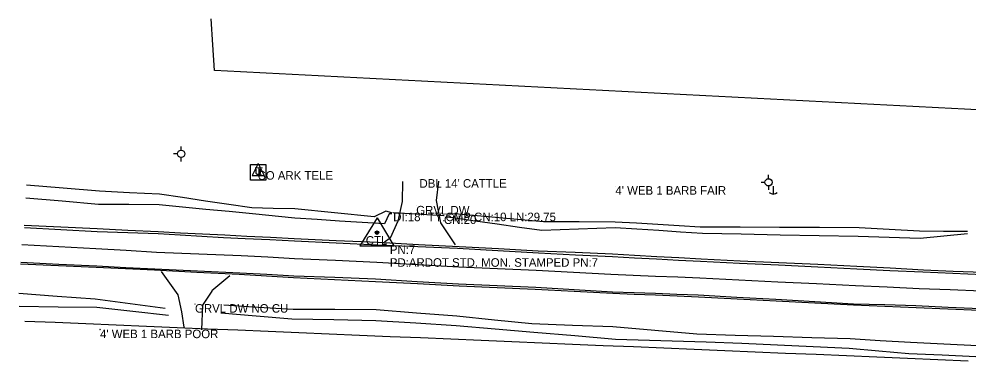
# Model space of a CAD drawing. Extents: x 1138803 to 1169983, y 1655906 to 1658226.
# Drawn here: x 1148268 to 1148823, y 1657454 to 1657654 of the extents above; entities that cross this region are included whole.
import ezdxf

# ---------------------------------------------------------------- set-up
doc = ezdxf.new("R2010")
doc.units = 0
for name, color, linetype in [('S_DITCHLINE', 7, 'Continuous'), ('S_DRG_PT_SYM', 7, 'Continuous'), ('S_DRIVEWAY', 7, 'Continuous'), ('S_EDGE_PAVEMENT', 7, 'Continuous'), ('S_GATE_ANNOT', 7, 'Continuous'), ('S_MSC_PT_SYM', 7, 'Continuous'), ('S_PAVEMENT_CROWN', 7, 'Continuous'), ('S_PRIMARY_CTL', 7, 'Continuous'), ('S_PRIMARY_CTL_ANNOT', 7, 'Continuous'), ('S_SHOULDER', 7, 'Continuous'), ('S_SIDE_DRAIN', 7, 'Continuous'), ('S_SIDE_DRAIN_ANNOT', 7, 'Continuous'), ('S_SURVEY_TEXT_ANNOT', 7, 'Continuous'), ('S_TELEPHONE_UTILITIES', 7, 'Continuous'), ('S_TREE', 7, 'Continuous'), ('S_UNDERGROUND_CABLE', 7, 'Continuous'), ('S_UTILITY_POLE', 7, 'Continuous'), ('S_UTILITY_POLE_ANNOT', 7, 'Continuous')]:
    doc.layers.add(name, color=color, linetype=linetype)

msp = doc.modelspace()

# ---------------------------------------------------------------- linework, layer by layer
at = {"layer": 'S_DITCHLINE'}
for points in [[(1148485.93, 1657540.92), (1148482.4, 1657541.89), (1148475.52, 1657538.62), (1148452.31, 1657540.88), (1148429.09, 1657543.15), (1148416.52, 1657543.47), (1148403.94, 1657543.8), (1148390.43, 1657545.79), (1148376.92, 1657547.79), (1148363.4, 1657549.79), (1148349.89, 1657551.79), (1148332.37, 1657552.66), (1148314.86, 1657553.54), (1148293.48, 1657555.35), (1148272.1, 1657557.17)], [(1148486.05, 1657540.23), (1148484.33, 1657540.22), (1148481.66, 1657534.47), (1148468.54, 1657535.28), (1148455.41, 1657536.08), (1148442.29, 1657536.89), (1148429.17, 1657537.7), (1148404.43, 1657540.36), (1148390.74, 1657541.65), (1148377.05, 1657542.93), (1148363.36, 1657544.22), (1148349.67, 1657545.51), (1148331.96, 1657545.67), (1148314.25, 1657545.83), (1148292.97, 1657547.67), (1148271.7, 1657549.5)], [(1148823.01, 1657528.61), (1148809.18, 1657527.24), (1148795.36, 1657525.87), (1148777.18, 1657526.41), (1148759, 1657526.95), (1148736.19, 1657527.41), (1148713.38, 1657527.87), (1148690.57, 1657528.33), (1148667.76, 1657528.79), (1148654.98, 1657529.62), (1148642.2, 1657530.45), (1148629.42, 1657531.28), (1148616.63, 1657532.11), (1148595.19, 1657531.29), (1148573.75, 1657530.47), (1148560.72, 1657532.34), (1148547.7, 1657534.2), (1148534.68, 1657536.07), (1148521.65, 1657537.93), (1148518.25, 1657538.29)], [(1148822.92, 1657529.88), (1148808.87, 1657529.97), (1148794.82, 1657530.07), (1148777.14, 1657531.08), (1148759.47, 1657532.09), (1148736.25, 1657532.21), (1148713.02, 1657532.33), (1148689.8, 1657532.45), (1148666.57, 1657532.57), (1148654.09, 1657533.3), (1148641.6, 1657534.04), (1148629.12, 1657534.77), (1148616.64, 1657535.51), (1148595.66, 1657535.58), (1148574.69, 1657535.66), (1148561.75, 1657536.84), (1148548.8, 1657538.03), (1148535.86, 1657539.21), (1148522.91, 1657540.4), (1148519.12, 1657539.89)], [(1148353.19, 1657484.82), (1148332.74, 1657487.54), (1148312.28, 1657490.26), (1148289.97, 1657492), (1148267.65, 1657493.74)], [(1148828.82, 1657463.09), (1148809.2, 1657464), (1148789.58, 1657464.92), (1148771.95, 1657465.99), (1148754.31, 1657467.06), (1148731.84, 1657467.76), (1148709.38, 1657468.47), (1148686.91, 1657469.18), (1148664.44, 1657469.89), (1148639.92, 1657472.02), (1148615.4, 1657474.15), (1148591.67, 1657474.99), (1148567.94, 1657475.83), (1148545.99, 1657478.12), (1148524.04, 1657480.4), (1148500.45, 1657482.25), (1148476.87, 1657484.1), (1148452.54, 1657484.22), (1148428.21, 1657484.35), (1148407.86, 1657485.56), (1148387.52, 1657486.78)], [(1148355.23, 1657480.77), (1148334.27, 1657483.12), (1148313.32, 1657485.47), (1148290.56, 1657485.74), (1148267.81, 1657486.01)], [(1148827.85, 1657456.65), (1148808.21, 1657457.48), (1148788.57, 1657458.32), (1148771.11, 1657459.92), (1148753.64, 1657461.51), (1148732.72, 1657462.45), (1148711.8, 1657463.39), (1148690.87, 1657464.33), (1148669.95, 1657465.26), (1148656.69, 1657465.65), (1148643.43, 1657466.03), (1148630.17, 1657466.42), (1148616.91, 1657466.8), (1148593.02, 1657468.8), (1148569.14, 1657470.79), (1148546.37, 1657472.78), (1148523.6, 1657474.78), (1148500.06, 1657476.24), (1148476.52, 1657477.7), (1148451.98, 1657478.17), (1148427.45, 1657478.63), (1148406.61, 1657480.36), (1148385.76, 1657482.09)]]:
    msp.add_lwpolyline(points, dxfattribs=at)
at = {"layer": 'S_DRG_PT_SYM'}
for points in [[(1148486.76, 1657541.01), (1148486.76, 1657541.06), (1148486.76, 1657541.01), (1148486.71, 1657541.01), (1148486.76, 1657541.01), (1148486.76, 1657540.96), (1148486.76, 1657541.01), (1148486.81, 1657541.01)], [(1148516.47, 1657539.33), (1148516.47, 1657539.38), (1148516.47, 1657539.33), (1148516.42, 1657539.33), (1148516.47, 1657539.33), (1148516.47, 1657539.28), (1148516.47, 1657539.33), (1148516.52, 1657539.33)]]:
    msp.add_lwpolyline(points, dxfattribs=at)
at = {"layer": 'S_DRIVEWAY'}
for points in [[(1148492.21, 1657559.26), (1148491.96, 1657547.46), (1148489.44, 1657536.08), (1148485.02, 1657526.13), (1148481.69, 1657523.77)], [(1148523.19, 1657522.09), (1148514.68, 1657535.04), (1148512.19, 1657548.05), (1148513.41, 1657559.47)], [(1148364.29, 1657473.87), (1148363.09, 1657482.96), (1148360.77, 1657492.85), (1148351.07, 1657506.46)], [(1148391.01, 1657504.01), (1148380.57, 1657495.14), (1148380.57, 1657495.03), (1148375.15, 1657486.8), (1148374.47, 1657472.43)]]:
    msp.add_lwpolyline(points, dxfattribs=at)
at = {"layer": 'S_EDGE_PAVEMENT'}
for points in [[(1148831.93, 1657504.6), (1148814.37, 1657505.33), (1148796.81, 1657506.06), (1148777.48, 1657507.02), (1148758.15, 1657507.98), (1148735.28, 1657509.08), (1148712.42, 1657510.18), (1148689.55, 1657511.27), (1148666.68, 1657512.37), (1148653.78, 1657513.05), (1148640.88, 1657513.73), (1148627.98, 1657514.41), (1148615.07, 1657515.1), (1148593.4, 1657516.16), (1148571.73, 1657517.22), (1148548.08, 1657518.57), (1148524.43, 1657519.93), (1148501.08, 1657520.94), (1148477.73, 1657521.95), (1148453.38, 1657523.17), (1148429.04, 1657524.38), (1148414.56, 1657524.99), (1148400.08, 1657525.59), (1148387.37, 1657526.33), (1148374.66, 1657527.07), (1148361.95, 1657527.81), (1148349.23, 1657528.56), (1148331.35, 1657529.19), (1148313.46, 1657529.83), (1148292.18, 1657530.97), (1148270.91, 1657532.11)], [(1148830.37, 1657484.61), (1148811.58, 1657485.5), (1148792.8, 1657486.39), (1148774.53, 1657486.94), (1148756.26, 1657487.5), (1148733.52, 1657488.79), (1148710.78, 1657490.07), (1148688.04, 1657491.36), (1148665.29, 1657492.65), (1148652.78, 1657493.12), (1148640.27, 1657493.59), (1148627.75, 1657494.06), (1148615.24, 1657494.52), (1148592.75, 1657495.85), (1148570.27, 1657497.18), (1148547.66, 1657498.14), (1148525.05, 1657499.09), (1148500.75, 1657500.55), (1148476.45, 1657502.01), (1148452.49, 1657502.94), (1148428.53, 1657503.86), (1148412.73, 1657504.74), (1148396.93, 1657505.61), (1148372.09, 1657506.75), (1148347.24, 1657507.89), (1148330.2, 1657508.73), (1148313.16, 1657509.58), (1148290.96, 1657510.7), (1148268.76, 1657511.81)]]:
    msp.add_lwpolyline(points, dxfattribs=at)
at = {"layer": 'S_MSC_PT_SYM'}
for points in [[(1148502.14, 1657560.62), (1148502.14, 1657560.67), (1148502.14, 1657560.62), (1148502.09, 1657560.62), (1148502.14, 1657560.62), (1148502.14, 1657560.57), (1148502.14, 1657560.62), (1148502.19, 1657560.62)], [(1148616.87, 1657556.52), (1148616.87, 1657556.57), (1148616.87, 1657556.52), (1148616.82, 1657556.52), (1148616.87, 1657556.52), (1148616.87, 1657556.47), (1148616.87, 1657556.52), (1148616.92, 1657556.52)], [(1148500.22, 1657544.94), (1148500.22, 1657544.99), (1148500.22, 1657544.94), (1148500.17, 1657544.94), (1148500.22, 1657544.94), (1148500.22, 1657544.89), (1148500.22, 1657544.94), (1148500.27, 1657544.94)], [(1148370.72, 1657487.45), (1148370.72, 1657487.5), (1148370.72, 1657487.45), (1148370.67, 1657487.45), (1148370.72, 1657487.45), (1148370.72, 1657487.4), (1148370.72, 1657487.45), (1148370.77, 1657487.45)], [(1148315.12, 1657472.53), (1148315.12, 1657472.58), (1148315.12, 1657472.53), (1148315.07, 1657472.53), (1148315.12, 1657472.53), (1148315.12, 1657472.48), (1148315.12, 1657472.53), (1148315.17, 1657472.53)]]:
    msp.add_lwpolyline(points, dxfattribs=at)
at = {"layer": 'S_PAVEMENT_CROWN'}
msp.add_lwpolyline([(1148831.07, 1657495.04), (1148812.84, 1657495.74), (1148794.61, 1657496.44), (1148776.01, 1657497.28), (1148757.42, 1657498.11), (1148734.65, 1657499.24), (1148711.89, 1657500.37), (1148689.13, 1657501.51), (1148666.37, 1657502.64), (1148653.34, 1657503.17), (1148640.31, 1657503.7), (1148627.29, 1657504.23), (1148614.26, 1657504.75), (1148592.36, 1657505.97), (1148570.45, 1657507.18), (1148547.8, 1657508.15), (1148525.15, 1657509.12), (1148501.16, 1657510.47), (1148477.17, 1657511.81), (1148453.02, 1657512.93), (1148428.88, 1657514.05), (1148413.3, 1657514.92), (1148397.72, 1657515.8), (1148372.95, 1657516.75), (1148348.18, 1657517.7), (1148330.45, 1657518.77), (1148312.72, 1657519.83), (1148291.06, 1657520.96), (1148269.4, 1657522.09)], dxfattribs=at)
at = {"layer": 'S_PRIMARY_CTL'}
for p, q in [((1148477.3, 1657538.02), (1148467.27, 1657521.51)), ((1148477.3, 1657538.02), (1148487.13, 1657521.51)), ((1148467.27, 1657521.51), (1148487.13, 1657521.51))]:
    msp.add_line(p, q, dxfattribs=at)
for radius in [1.04, 0.609, 0.344]:
    msp.add_circle((1148477.3, 1657529.32), radius, dxfattribs=at)
at = {"layer": 'S_SHOULDER'}
for points in [[(1148832.19, 1657505.94), (1148814.7, 1657506.63), (1148797.2, 1657507.32), (1148777.73, 1657508.41), (1148758.27, 1657509.51), (1148735.45, 1657510.57), (1148712.63, 1657511.63), (1148689.82, 1657512.69), (1148667, 1657513.75), (1148654.02, 1657514.47), (1148641.04, 1657515.2), (1148628.06, 1657515.93), (1148615.09, 1657516.65), (1148593.34, 1657517.58), (1148571.59, 1657518.5), (1148548.47, 1657519.74), (1148525.35, 1657520.98), (1148501.63, 1657522.24), (1148477.91, 1657523.51), (1148453.35, 1657524.58), (1148428.78, 1657525.65), (1148414.97, 1657526.39), (1148401.15, 1657527.12), (1148388.16, 1657527.76), (1148375.16, 1657528.4), (1148362.17, 1657529.04), (1148349.17, 1657529.68), (1148331.34, 1657530.61), (1148313.5, 1657531.54), (1148292.13, 1657532.52), (1148270.76, 1657533.5)], [(1148830.05, 1657483.76), (1148811.47, 1657484.54), (1148792.89, 1657485.32), (1148774.59, 1657486.06), (1148756.28, 1657486.79), (1148733.58, 1657487.99), (1148710.88, 1657489.2), (1148688.17, 1657490.41), (1148665.47, 1657491.61), (1148652.93, 1657492.11), (1148640.39, 1657492.61), (1148627.84, 1657493.11), (1148615.3, 1657493.62), (1148592.62, 1657494.85), (1148569.93, 1657496.08), (1148547.68, 1657497.06), (1148525.43, 1657498.04), (1148500.94, 1657499.28), (1148476.45, 1657500.53), (1148452.41, 1657501.69), (1148428.37, 1657502.85), (1148412.5, 1657503.78), (1148396.63, 1657504.71), (1148371.82, 1657506), (1148347.02, 1657507.29), (1148329.96, 1657508.04), (1148312.89, 1657508.8), (1148290.75, 1657509.81), (1148268.61, 1657510.82)]]:
    msp.add_lwpolyline(points, dxfattribs=at)
at = {"layer": 'S_SIDE_DRAIN'}
msp.add_line((1148486.76, 1657541.01), (1148516.47, 1657539.33), dxfattribs=at)
at = {"layer": 'S_TELEPHONE_UTILITIES'}
msp.add_lwpolyline([(1148403.12, 1657560.09), (1148403.12, 1657569.09), (1148412.12, 1657569.09), (1148412.12, 1657560.09)], close=True, dxfattribs=at)
at = {"layer": 'S_TREE'}
for points in [[(1148836.34, 1657600.82), (1148821.2, 1657601.6), (1148806.06, 1657602.38), (1148790.92, 1657603.16), (1148775.78, 1657603.95), (1148760.64, 1657604.73), (1148745.5, 1657605.51), (1148730.37, 1657606.29), (1148715.23, 1657607.07), (1148700.09, 1657607.85), (1148684.95, 1657608.63), (1148669.81, 1657609.42), (1148654.67, 1657610.2), (1148639.53, 1657610.98), (1148624.39, 1657611.76), (1148609.25, 1657612.54), (1148594.12, 1657613.32), (1148578.98, 1657614.11), (1148563.84, 1657614.89), (1148548.7, 1657615.67), (1148533.56, 1657616.45), (1148518.42, 1657617.23), (1148503.28, 1657618.01), (1148488.14, 1657618.8), (1148473, 1657619.58), (1148457.87, 1657620.36), (1148442.73, 1657621.14), (1148427.59, 1657621.92), (1148412.45, 1657622.7), (1148397.31, 1657623.48), (1148382.17, 1657624.27), (1148381.19, 1657639.31), (1148380.22, 1657654.36)], [(1148823.4, 1657454.15), (1148805.58, 1657454.9), (1148787.77, 1657455.64), (1148769.95, 1657456.39), (1148752.13, 1657457.14), (1148734.32, 1657457.89), (1148716.5, 1657458.64), (1148698.68, 1657459.39), (1148680.87, 1657460.14), (1148663.05, 1657460.88), (1148645.24, 1657461.63), (1148627.42, 1657462.38), (1148609.6, 1657463.13), (1148591.79, 1657463.88), (1148573.97, 1657464.63), (1148556.16, 1657465.38), (1148538.34, 1657466.12), (1148520.52, 1657466.87), (1148502.71, 1657467.62), (1148484.89, 1657468.37), (1148467.07, 1657469.12), (1148449.26, 1657469.87), (1148431.44, 1657470.61), (1148413.63, 1657471.36), (1148395.81, 1657472.11), (1148377.99, 1657472.86), (1148360.18, 1657473.61), (1148342.36, 1657474.36), (1148324.55, 1657475.11), (1148306.73, 1657475.85), (1148288.91, 1657476.6), (1148271.1, 1657477.35)]]:
    msp.add_lwpolyline(points, dxfattribs=at)
at = {"layer": 'S_UNDERGROUND_CABLE'}
for p, q in [((1148407.69, 1657569.81), (1148404.17, 1657562.72)), ((1148406.49, 1657563.96), (1148406.49, 1657566.4)), ((1148407.69, 1657569.81), (1148411.18, 1657562.72)), ((1148408.86, 1657566.4), (1148408.86, 1657563.96)), ((1148404.17, 1657562.72), (1148411.18, 1657562.72)), ((1148407.11, 1657563.3), (1148406.49, 1657563.96)), ((1148408.31, 1657563.3), (1148407.11, 1657563.3)), ((1148408.86, 1657563.96), (1148408.31, 1657563.3))]:
    msp.add_line(p, q, dxfattribs=at)
at = {"layer": 'S_UTILITY_POLE'}
for p, q in [((1148362.58, 1657577.53), (1148362.58, 1657579.78)), ((1148360.49, 1657575.4), (1148358.16, 1657575.4)), ((1148362.66, 1657570.98), (1148362.66, 1657573.31)), ((1148706.53, 1657560.86), (1148706.53, 1657563.11)), ((1148704.44, 1657558.73), (1148702.11, 1657558.73)), ((1148706.61, 1657554.32), (1148706.61, 1657556.64)), ((1148709.19, 1657556.59), (1148709.19, 1657551.86))]:
    msp.add_line(p, q, dxfattribs=at)
for centre in [(1148362.58, 1657575.42), (1148706.53, 1657558.75)]:
    msp.add_circle(centre, 2.13, dxfattribs=at)
msp.add_arc((1148709.26, 1657555.29), 3.41, 226.3972, 313.6028, dxfattribs=at)

# ---------------------------------------------------------------- texts
at = {"layer": 'S_GATE_ANNOT'}
msp.add_text("DBL 14' CATTLE", height=5, dxfattribs=at).set_placement((1148502.14, 1657555.62))
at = {"layer": 'S_PRIMARY_CTL'}
msp.add_text('CTL', height=5, rotation=360, dxfattribs=at).set_placement((1148470.71, 1657522.24))
at = {"layer": 'S_PRIMARY_CTL_ANNOT'}
for s, p in [('PN:7', (1148484.8, 1657516.82)), ('PD:ARDOT STD. MON. STAMPED PN:7', (1148484.8, 1657509.32))]:
    msp.add_text(s, height=5, dxfattribs=at).set_placement(p)
at = {"layer": 'S_SIDE_DRAIN_ANNOT'}
for s, p in [('DI:18" TY:CMP CN:10 LN:29.75', (1148486.76, 1657536.01)), ('CN:20', (1148516.47, 1657534.33))]:
    msp.add_text(s, height=5, dxfattribs=at).set_placement(p)
at = {"layer": 'S_SURVEY_TEXT_ANNOT'}
for s, p in [("4' WEB 1 BARB FAIR", (1148616.87, 1657551.52)), ('GRVL DW', (1148500.22, 1657539.94)), ('GRVL DW NO CU', (1148370.72, 1657482.45)), ("4' WEB 1 BARB POOR", (1148315.12, 1657467.53))]:
    msp.add_text(s, height=5, dxfattribs=at).set_placement(p)
at = {"layer": 'S_TELEPHONE_UTILITIES'}
msp.add_text('T', height=6, rotation=360, dxfattribs=at).set_placement((1148405.68, 1657561.59))
at = {"layer": 'S_UTILITY_POLE_ANNOT'}
msp.add_text('SO ARK TELE', height=5, dxfattribs=at).set_placement((1148407.69, 1657560.28))

doc.saveas('drawing.dxf')
